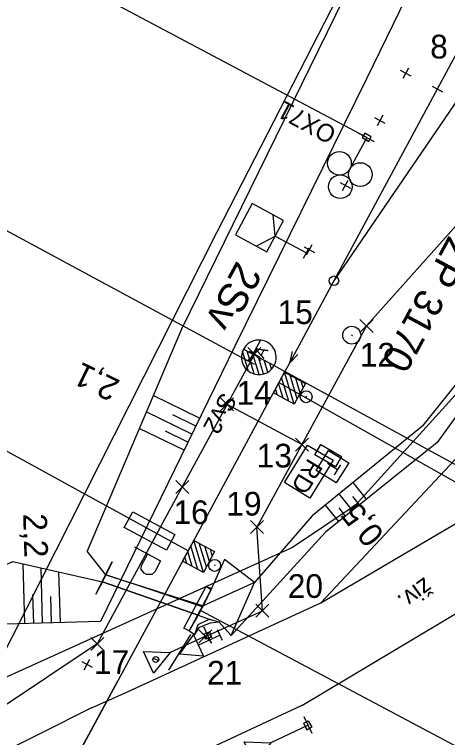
# Model space of a CAD drawing. Extents: x -795094 to -794639, y -1135368 to -1134681.
# Drawn here: x -794897.6 to -794861.1, y -1135032.7 to -1134971.7 of the extents above; entities that cross this region are included whole.
import ezdxf

# ---------------------------------------------------------------- set-up
doc = ezdxf.new("R2010")
doc.units = 0
for name, color, linetype in [('0381KM005-009P - Vrstva 1', 7, 'Continuous'), ('0381KM005-009P - Vrstva 12', 7, 'Continuous'), ('0381KM005-009P - Vrstva 13', 7, 'Continuous'), ('0381KM005-009P - Vrstva 19', 7, 'Continuous'), ('0381KM005-009P - Vrstva 2', 7, 'Continuous'), ('0381KM005-009P - Vrstva 23', 7, 'Continuous'), ('0381KM005-009P - Vrstva 25', 7, 'Continuous'), ('0381KM005-009P - Vrstva 28', 7, 'Continuous'), ('0381KM005-009P - Vrstva 3', 7, 'Continuous'), ('0381KM005-009P - Vrstva 33', 7, 'Continuous'), ('0381KM005-009P - Vrstva 4', 7, 'Continuous'), ('0381KM005-009P - Vrstva 48', 7, 'Continuous'), ('0381KM005-009P - Vrstva 49', 7, 'Continuous'), ('0381KM005-009P - Vrstva 51', 7, 'Continuous'), ('0381KM005-009P - Vrstva 6', 7, 'Continuous'), ('0381KM005-009P - Vrstva 7', 7, 'Continuous'), ('0381KM005-009P - Vrstva 8', 7, 'Continuous'), ('Default', 7, 'Continuous'), ('hran DP - hran DP', 7, 'Continuous'), ('PSR_C2_1_Lomove_body_Strunkovice - Vrstva 60', 7, 'Continuous'), ('PSR_C2_1_trasa_Strunkovice - Kabelová trasa', 7, 'Continuous'), ('vyt_sit - ohrožené', 7, 'Continuous')]:
    doc.layers.add(name, color=color, linetype=linetype)

msp = doc.modelspace()

# ---------------------------------------------------------------- linework, layer by layer
at = {"layer": '0381KM005-009P - Vrstva 1'}
for points in [[(-794788.584, -1134840.279), (-794803.188, -1134868.16), (-794810.376, -1134881.864), (-794818.661, -1134897.596), (-794826.62, -1134912.502), (-794834.335, -1134926.852), (-794861.916, -1134977.994)], [(-794861.916, -1134977.994), (-794870.638, -1134994.169), (-794874.381, -1135001.111), (-794874.769, -1135001.818)], [(-794860.098, -1134978.738), (-794870.638, -1134994.169), (-794874.381, -1135001.111), (-794874.769, -1135001.818)], [(-794874.769, -1135001.818), (-794875.274, -1135002.762), (-794882.938, -1135016.954), (-794888.877, -1135027.929)], [(-794888.877, -1135027.929), (-794896.922, -1135042.829), (-794900.945, -1135050.279), (-794913.191, -1135072.813), (-794931.084, -1135105.636), (-794935.694, -1135114.258)]]:
    msp.add_lwpolyline(points, dxfattribs=at)
at = {"layer": '0381KM005-009P - Vrstva 12'}
for p, q in [((-794868.254, -1134982.095), (-794868.254, -1134982.093)), ((-794867.486, -1134982.03), (-794867.487, -1134982.039)), ((-794867.706, -1134982.41), (-794867.706, -1134982.408)), ((-794881.135, -1135023.787), (-794881.134, -1135023.786)), ((-794881.463, -1135024.402), (-794881.591, -1135023.948)), ((-794872.921, -1135032.058), (-794872.907, -1135032.064)), ((-794872.503, -1135031.848), (-794872.503, -1135031.85))]:
    msp.add_line(p, q, dxfattribs=at)
for points in [[(-794868.02, -1134981.72), (-794868.254, -1134982.095), (-794867.706, -1134982.41), (-794867.486, -1134982.03), (-794868.02, -1134981.72), (-794868.02, -1134981.729), (-794868.254, -1134982.093), (-794867.706, -1134982.408), (-794867.487, -1134982.039), (-794868.02, -1134981.729)], [(-794881.591, -1135023.948), (-794881.135, -1135023.787), (-794880.98, -1135024.241), (-794881.456, -1135024.394), (-794881.591, -1135023.948), (-794881.591, -1135023.948), (-794881.134, -1135023.786), (-794880.982, -1135024.244), (-794880.98, -1135024.241)], [(-794880.982, -1135024.244), (-794881.463, -1135024.402), (-794881.456, -1135024.394)], [(-794873.17, -1135031.494), (-794872.804, -1135031.314), (-794872.503, -1135031.848), (-794872.921, -1135032.058), (-794873.17, -1135031.494), (-794873.172, -1135031.504), (-794872.804, -1135031.31), (-794872.503, -1135031.85), (-794872.907, -1135032.064), (-794873.172, -1135031.504)]]:
    msp.add_lwpolyline(points, dxfattribs=at)
at = {"layer": '0381KM005-009P - Vrstva 13'}
msp.add_line((-794884.558, -1135027.039), (-794882.707, -1135024.01), dxfattribs=at)
for points in [[(-794882.372, -1135024.009), (-794882.1, -1135023.181), (-794881.151, -1135022.716), (-794880.338, -1135022.961)], [(-794882.372, -1135024.009), (-794881.98, -1135023.399), (-794881.043, -1135023.044), (-794880.338, -1135022.961)]]:
    msp.add_lwpolyline(points, dxfattribs=at)
at = {"layer": '0381KM005-009P - Vrstva 19'}
for p, q in [((-794881.719, -1135021.674), (-794889.883, -1135018.985)), ((-794889.878, -1135018.973), (-794881.683, -1135021.602)), ((-794882.104, -1135022.384), (-794890.171, -1135019.586)), ((-794890.162, -1135019.567), (-794882.105, -1135022.384)), ((-794880.995, -1135020.223), (-794880.962, -1135020.146)), ((-794881.932, -1135021.971), (-794835.064, -1135046.885))]:
    msp.add_line(p, q, dxfattribs=at)
for points in [[(-794890.171, -1135019.586), (-794890.737, -1135020.613), (-794889.348, -1135017.893), (-794889.878, -1135018.973)], [(-794890.171, -1135019.586), (-794890.162, -1135019.567), (-794889.883, -1135018.985), (-794889.878, -1135018.973)], [(-794881.427, -1135019.977), (-794880.962, -1135020.146), (-794881.683, -1135021.602), (-794881.719, -1135021.674), (-794882.105, -1135022.384), (-794882.104, -1135022.384), (-794882.859, -1135023.7)]]:
    msp.add_lwpolyline(points, dxfattribs=at)
msp.add_lwpolyline([(-794881.427, -1135019.977), (-794880.995, -1135020.223), (-794882.859, -1135023.7), (-794883.292, -1135023.475)], close=True, dxfattribs=at)
at = {"layer": '0381KM005-009P - Vrstva 2'}
for p, q in [((-794862.356, -1134977.757), (-794861.476, -1134978.231)), ((-794860.098, -1134978.738), (-794870.638, -1134994.169)), ((-794878.261, -1134999.938), (-794875.685, -1135001.328)), ((-794878.261, -1134999.938), (-794878.261, -1134999.938)), ((-794877.832, -1135001.815), (-794878.34, -1135000.119)), ((-794877.369, -1135002.038), (-794877.947, -1135000.107)), ((-794876.956, -1135002.093), (-794877.474, -1135000.362)), ((-794876.576, -1135002.038), (-794877, -1135000.617)), ((-794876.224, -1135001.888), (-794876.528, -1135000.873)), ((-794875.905, -1135001.629), (-794876.055, -1135001.128)), ((-794875.685, -1135001.327), (-794874.769, -1135001.818)), ((-794830.917, -1135025.882), (-794874.769, -1135001.818))]:
    msp.add_line(p, q, dxfattribs=at)
for points in [[(-794861.916, -1134977.994), (-794870.638, -1134994.169), (-794874.381, -1135001.111), (-794874.769, -1135001.818)], [(-794874.15, -1135000.138), (-794874.381, -1135001.111), (-794873.695, -1135000.384)]]:
    msp.add_lwpolyline(points, dxfattribs=at)
msp.add_circle((-794870.638, -1134994.169), 0.4, dxfattribs=at)
for centre, radius, start, end in [((-794876.971, -1135000.632), 1.462, 331.59731, 152.06683), ((-794876.972, -1135000.633), 1.464, 151.68684, 331.64769)]:
    msp.add_arc(centre, radius, start, end, dxfattribs=at)
at = {"layer": '0381KM005-009P - Vrstva 23'}
msp.add_lwpolyline([(-794874.822, -1135011.194), (-794872.86, -1135008.042), (-794870.713, -1135009.3), (-794872.684, -1135012.526)], close=True, dxfattribs=at)
at = {"layer": '0381KM005-009P - Vrstva 25'}
msp.add_lwpolyline([(-794870.013, -1135008.995), (-794870.519, -1135009.858), (-794872.245, -1135008.847), (-794871.739, -1135007.984), (-794870.013, -1135008.995)], dxfattribs=at)
at = {"layer": '0381KM005-009P - Vrstva 28'}
for p, q in [((-794872.954, -1135003.918), (-794873.002, -1135004.006)), ((-794880.68, -1135018.146), (-794880.728, -1135018.234))]:
    msp.add_line(p, q, dxfattribs=at)
for centre in [(-794872.978, -1135003.962), (-794880.704, -1135018.19)]:
    msp.add_circle(centre, 0.5, dxfattribs=at)
at = {"layer": '0381KM005-009P - Vrstva 3'}
for p, q in [((-794882.938, -1135016.954), (-794926.069, -1134993.289)), ((-794873.988, -1135004.591), (-794874.8, -1135001.882)), ((-794874.454, -1135004.34), (-794875.051, -1135002.348)), ((-794873.736, -1135004.125), (-794874.333, -1135002.133)), ((-794873.484, -1135003.657), (-794873.866, -1135002.385)), ((-794874.922, -1135004.088), (-794875.303, -1135002.816)), ((-794873.233, -1135003.191), (-794873.399, -1135002.637)), ((-794875.388, -1135003.836), (-794875.554, -1135003.282)), ((-794882.118, -1135018.532), (-794882.715, -1135016.54)), ((-794881.652, -1135018.783), (-794882.464, -1135016.074)), ((-794881.4, -1135018.317), (-794881.997, -1135016.325)), ((-794882.586, -1135018.28), (-794882.967, -1135017.008)), ((-794881.148, -1135017.849), (-794881.53, -1135016.577)), ((-794880.897, -1135017.383), (-794881.063, -1135016.829)), ((-794883.052, -1135018.028), (-794883.218, -1135017.474))]:
    msp.add_line(p, q, dxfattribs=at)
for points in [[(-794875.748, -1135003.642), (-794874.8, -1135001.882), (-794873.039, -1135002.831), (-794873.988, -1135004.591)], [(-794883.412, -1135017.834), (-794882.464, -1135016.074), (-794880.703, -1135017.023), (-794881.652, -1135018.783)]]:
    msp.add_lwpolyline(points, close=True, dxfattribs=at)
msp.add_lwpolyline([(-794875.274, -1135002.762), (-794845.796, -1135019.381), (-794847.666, -1135022.537), (-794833.282, -1135030.23)], dxfattribs=at)
at = {"layer": '0381KM005-009P - Vrstva 33'}
for p, q in [((-794870.346, -1135010.122), (-794871.194, -1135009.594)), ((-794870.081, -1135009.698), (-794870.61, -1135010.547))]:
    msp.add_line(p, q, dxfattribs=at)
for points in [[(-794869.393, -1135009.537), (-794870.449, -1135011.235), (-794872.147, -1135010.179), (-794871.091, -1135008.481), (-794869.393, -1135009.537)], [(-794887.47, -1135016.622), (-794885.263, -1135017.812)], [(-794886.847, -1135018.143), (-794886.352, -1135017.225)], [(-794885.757, -1135018.73), (-794886, -1135018.959), (-794886.462, -1135018.96), (-794886.657, -1135018.856), (-794886.918, -1135018.464), (-794886.847, -1135018.143)], [(-794885.263, -1135017.812), (-794885.757, -1135018.73)]]:
    msp.add_lwpolyline(points, dxfattribs=at)
msp.add_lwpolyline([(-794884.068, -1135015.578), (-794884.775, -1135016.889), (-794888.322, -1135014.977), (-794887.615, -1135013.666)], close=True, dxfattribs=at)
at = {"layer": '0381KM005-009P - Vrstva 4'}
for p, q in [((-794880.964, -1135024.789), (-794881.61, -1135023.373)), ((-794885.444, -1135026.218), (-794885.902, -1135026.044)), ((-794896.922, -1135042.829), (-794888.877, -1135027.929)), ((-794872.484, -1135032.382), (-794873.138, -1135030.97))]:
    msp.add_line(p, q, dxfattribs=at)
for points in [[(-794881.287, -1135024.081), (-794884.446, -1135025.533), (-794885.857, -1135027.268), (-794886.697, -1135025.455), (-794884.446, -1135025.533)], [(-794872.811, -1135031.676), (-794875.963, -1135033.145), (-794877.364, -1135034.887), (-794878.213, -1135033.078), (-794875.963, -1135033.145)]]:
    msp.add_lwpolyline(points, dxfattribs=at)
msp.add_circle((-794885.672, -1135026.13), 0.248, dxfattribs=at)
at = {"layer": '0381KM005-009P - Vrstva 48'}
for p, q in [((-794881.969, -1135005.772), (-794885.885, -1135003.859)), ((-794882.628, -1135007.12), (-794886.473, -1135005.241)), ((-794882.298, -1135006.446), (-794884.239, -1135005.498)), ((-794883.286, -1135008.468), (-794887.061, -1135006.624)), ((-794882.957, -1135007.794), (-794884.862, -1135006.863)), ((-794867.896, -1135012.612), (-794869.029, -1135011.202)), ((-794869.065, -1135013.552), (-794870.19, -1135012.152)), ((-794868.48, -1135013.082), (-794869.045, -1135012.379)), ((-794870.234, -1135014.491), (-794871.352, -1135013.101)), ((-794869.649, -1135014.022), (-794870.21, -1135013.324)), ((-794896.711, -1135023.102), (-794896.862, -1135018.048)), ((-794895.212, -1135023.057), (-794895.351, -1135018.396)), ((-794893.713, -1135023.012), (-794893.84, -1135018.743)), ((-794895.962, -1135023.079), (-794896.034, -1135020.651)), ((-794894.462, -1135023.035), (-794894.529, -1135020.802))]:
    msp.add_line(p, q, dxfattribs=at)
at = {"layer": '0381KM005-009P - Vrstva 49'}
for p, q in [((-794855.687, -1134952.034), (-794867.891, -1134977.129)), ((-794868.24, -1134967.149), (-794883.505, -1134998.267)), ((-794867.891, -1134977.129), (-794879, -1134999.695)), ((-794863.119, -1135006.371), (-794848.162, -1134987.718)), ((-794883.505, -1134998.267), (-794891.468, -1135016.979)), ((-794879, -1134999.695), (-794890.343, -1135022.912)), ((-794858.241, -1135002.662), (-794861.943, -1135007.826)), ((-794863.119, -1135006.371), (-794872.471, -1135014.016)), ((-794861.943, -1135007.826), (-794871.359, -1135015.396)), ((-794872.471, -1135014.016), (-794877.347, -1135019.619)), ((-794871.359, -1135015.396), (-794879.305, -1135024.095)), ((-794889.878, -1135018.973), (-794891.468, -1135016.979)), ((-794890.737, -1135020.613), (-794890.171, -1135019.586)), ((-794877.347, -1135019.619), (-794881.683, -1135021.602)), ((-794881.683, -1135021.602), (-794880.962, -1135020.146)), ((-794879.305, -1135024.095), (-794877.347, -1135019.619)), ((-794882.859, -1135023.7), (-794882.104, -1135022.384)), ((-794882.104, -1135022.384), (-794881.151, -1135022.716)), ((-794882.859, -1135023.7), (-794882.372, -1135024.009))]:
    msp.add_line(p, q, dxfattribs=at)
for points in [[(-794877.347, -1135019.619), (-794879.878, -1135017.7), (-794880.962, -1135020.146)], [(-794902.249, -1135032.148), (-794906.037, -1135021.561), (-794897.72, -1135017.851), (-794890.171, -1135019.586)], [(-794889.878, -1135018.973), (-794889.348, -1135017.893), (-794890.737, -1135020.613)], [(-794890.343, -1135022.912), (-794902.371, -1135023.27), (-794902.249, -1135032.148)], [(-794882.372, -1135024.009), (-794882.1, -1135023.181), (-794881.151, -1135022.716), (-794880.338, -1135022.961), (-794879.305, -1135024.095)]]:
    msp.add_lwpolyline(points, dxfattribs=at)
at = {"layer": '0381KM005-009P - Vrstva 51'}
for p, q in [((-794855.733, -1135004.243), (-794871.739, -1135021.338)), ((-794873.355, -1135030.02), (-794856.162, -1135019.751)), ((-794880.039, -1135024.538), (-794880.457, -1135023.63)), ((-794891.1, -1135030.195), (-794888.357, -1135028.995))]:
    msp.add_line(p, q, dxfattribs=at)
for points in [[(-794871.739, -1135021.338), (-794845.859, -1135006.134), (-794837.373, -1134998.386), (-794824.29, -1134983.577), (-794790.5, -1134931.648), (-794766.188, -1134894.559)], [(-794888.357, -1135028.995), (-794871.739, -1135021.338)], [(-794880.248, -1135024.084), (-794882.064, -1135024.921), (-794882.483, -1135024.013), (-794883.654, -1135025.653), (-794881.646, -1135025.829), (-794882.064, -1135024.921)], [(-794891.1, -1135030.195), (-794903.856, -1135036.615), (-794914.152, -1135043.554), (-794921.867, -1135051.409), (-794929.42, -1135063.919)], [(-794873.355, -1135030.02), (-794894.173, -1135039.744)]]:
    msp.add_lwpolyline(points, dxfattribs=at)
at = {"layer": '0381KM005-009P - Vrstva 6'}
for p, q in [((-794877.804, -1135000.976), (-794918.759, -1134978.921)), ((-794876.865, -1134999.233), (-794877.804, -1135000.976)), ((-794878.244, -1135000.739), (-794877.364, -1135001.213))]:
    msp.add_line(p, q, dxfattribs=at)
at = {"layer": '0381KM005-009P - Vrstva 7'}
for p, q in [((-794864.338, -1134976.225), (-794864.812, -1134977.105)), ((-794864.135, -1134976.902), (-794865.015, -1134976.428)), ((-794866.304, -1134980.89), (-794867.184, -1134980.416)), ((-794866.507, -1134980.213), (-794866.981, -1134981.093)), ((-794870.117, -1134985.893), (-794869.237, -1134986.367)), ((-794869.914, -1134986.57), (-794869.44, -1134985.69)), ((-794875.599, -1134990.397), (-794872.958, -1134991.821)), ((-794873.195, -1134992.261), (-794872.721, -1134991.381)), ((-794873.156, -1134991.305), (-794872.276, -1134991.779)), ((-794872.953, -1134991.982), (-794872.479, -1134991.102)), ((-794877.59, -1135000.797), (-794877.116, -1134999.917)), ((-794877.793, -1135000.12), (-794876.913, -1135000.594)), ((-794891.902, -1135026.309), (-794891.022, -1135026.783)), ((-794891.699, -1135026.986), (-794891.225, -1135026.106))]:
    msp.add_line(p, q, dxfattribs=at)
for points in [[(-794875.599, -1134990.397), (-794874.887, -1134989.077), (-794877.527, -1134987.653), (-794878.951, -1134990.294), (-794876.311, -1134991.718), (-794875.599, -1134990.397)], [(-794877.192, -1134991.242), (-794875.599, -1134990.397), (-794875.769, -1134988.601)]]:
    msp.add_lwpolyline(points, dxfattribs=at)
at = {"layer": '0381KM005-009P - Vrstva 8'}
for p, q in [((-794867.871, -1134982.096), (-794910.227, -1134959.525)), ((-794867.211, -1134982.452), (-794868.531, -1134981.74)), ((-794867.871, -1134982.096), (-794869.295, -1134984.737))]:
    msp.add_line(p, q, dxfattribs=at)
for centre in [(-794870.175, -1134984.262), (-794868.415, -1134985.211), (-794870.102, -1134986.233)]:
    msp.add_circle(centre, 1, dxfattribs=at)
at = {"layer": 'hran DP - hran DP'}
for p, q in [((-794880.53, -1134990.11), (-794861.46, -1134953)), ((-794899.86, -1135028.32), (-794880.53, -1134990.11)), ((-794854.54, -1134997.31), (-794868.85, -1135013.13)), ((-794868.85, -1135013.13), (-794874.12, -1135016.68)), ((-794874.12, -1135016.68), (-794899.86, -1135028.32))]:
    msp.add_line(p, q, dxfattribs=at)
at = {"layer": 'PSR_C2_1_Lomove_body_Strunkovice - Vrstva 60'}
for p, q in [((-794868.441, -1134998.53), (-794867.341, -1134997.43)), ((-794867.341, -1134998.53), (-794868.441, -1134997.43)), ((-794877.903, -1135000.907), (-794876.803, -1134999.807)), ((-794876.803, -1135000.907), (-794877.903, -1134999.807)), ((-794880.208, -1135005.156), (-794879.108, -1135004.056)), ((-794879.108, -1135005.156), (-794880.208, -1135004.056)), ((-794873.894, -1135008.541), (-794872.794, -1135007.441)), ((-794872.794, -1135008.541), (-794873.894, -1135007.441)), ((-794883.986, -1135012.121), (-794882.886, -1135011.021)), ((-794882.886, -1135012.121), (-794883.986, -1135011.021)), ((-794877.684, -1135015.5), (-794876.584, -1135014.4)), ((-794876.584, -1135015.5), (-794877.684, -1135014.4)), ((-794877.217, -1135022.561), (-794876.117, -1135021.461)), ((-794876.117, -1135022.561), (-794877.217, -1135021.461)), ((-794882.036, -1135024.723), (-794880.936, -1135023.623)), ((-794880.936, -1135024.723), (-794882.036, -1135023.623)), ((-794891.153, -1135025.365), (-794890.053, -1135024.265)), ((-794890.053, -1135025.365), (-794891.153, -1135024.265))]:
    msp.add_line(p, q, dxfattribs=at)
at = {"layer": 'PSR_C2_1_trasa_Strunkovice - Kabelová trasa'}
for p, q in [((-794859.567, -1134988.659), (-794867.891, -1134997.98)), ((-794867.891, -1134997.98), (-794877.134, -1135014.95)), ((-794877.353, -1135000.357), (-794883.436, -1135011.571)), ((-794883.436, -1135011.571), (-794890.603, -1135024.815)), ((-794890.603, -1135024.815), (-794904.752, -1135034.227))]:
    msp.add_line(p, q, dxfattribs=at)
for points in [[(-794873.344, -1135007.991), (-794879.658, -1135004.606)], [(-794881.486, -1135024.173), (-794876.667, -1135022.011), (-794877.134, -1135014.95)]]:
    msp.add_lwpolyline(points, dxfattribs=at)
at = {"layer": 'vyt_sit - ohrožené'}
msp.add_line((-794869.114, -1134998.723), (-794869.162, -1134998.811), dxfattribs=at)
msp.add_circle((-794869.138, -1134998.767), 0.756, dxfattribs=at)

# ---------------------------------------------------------------- texts
at = {"layer": '0381KM005-009P - Vrstva 2'}
msp.add_text('2Sv', height=2.5, rotation=241.66726, dxfattribs=at).set_placement((-794878.811, -1134992.402))
at = {"layer": '0381KM005-009P - Vrstva 23'}
msp.add_text('RD', height=1.5, rotation=238.57618, dxfattribs=at).set_placement((-794872.79, -1135009.076))
at = {"layer": '0381KM005-009P - Vrstva 48'}
for s, rotation, p in [('2,1', 153.96151, (-794888.582, -1135002.628)), ('0,5', 128.79757, (-794866.307, -1135015.568)), ('2,2', 271.70484, (-794896.86, -1135013.833))]:
    msp.add_text(s, height=2, rotation=rotation, dxfattribs=at).set_placement(p)
at = {"layer": '0381KM005-009P - Vrstva 51'}
msp.add_text('živ.', height=1.5, rotation=215.84894, dxfattribs=at).set_placement((-794862.992, -1135019.127))
at = {"layer": '0381KM005-009P - Vrstva 6'}
for s, height, rotation, p in [('  A ', 1, 61.67637, (-794876.924, -1135001.45)), ('Sv2', 1.5, 241.67637, (-794880.085, -1135003.496))]:
    msp.add_text(s, height=height, rotation=rotation, dxfattribs=at).set_placement(p)
at = {"layer": '0381KM005-009P - Vrstva 8'}
msp.add_text('OX71', height=1.5, rotation=151.66525, dxfattribs=at).set_placement((-794870.315, -1134981.384))
at = {"layer": 'Default'}
for s, p in [('8', (-794862.517, -1134975.417)), ('15', (-794875.391, -1134997.825)), ('12', (-794868.459, -1135001.411)), ('14', (-794878.862, -1135004.634)), ('13', (-794877.154, -1135009.926)), ('19', (-794879.722, -1135013.983)), ('16', (-794884.176, -1135014.701)), ('20', (-794874.535, -1135020.93)), ('17', (-794890.887, -1135027.347)), ('21', (-794881.344, -1135028.242))]:
    msp.add_text(s, height=2, dxfattribs=at).set_placement(p)
at = {"layer": 'vyt_sit - ohrožené'}
msp.add_text('ŽP 3170', height=2.4, rotation=241.67136, dxfattribs=at).set_placement((-794860.936, -1134990.309))

doc.saveas('drawing.dxf')
